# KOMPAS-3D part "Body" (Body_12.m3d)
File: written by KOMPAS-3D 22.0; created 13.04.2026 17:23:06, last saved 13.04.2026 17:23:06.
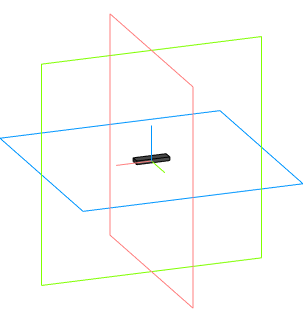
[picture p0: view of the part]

Document properties: Автор: Andrey; Полное имя файла: C:\Users\User1\Documents\Body_12.m3d

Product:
- Part/product: Body

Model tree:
1. Операция без истории:1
